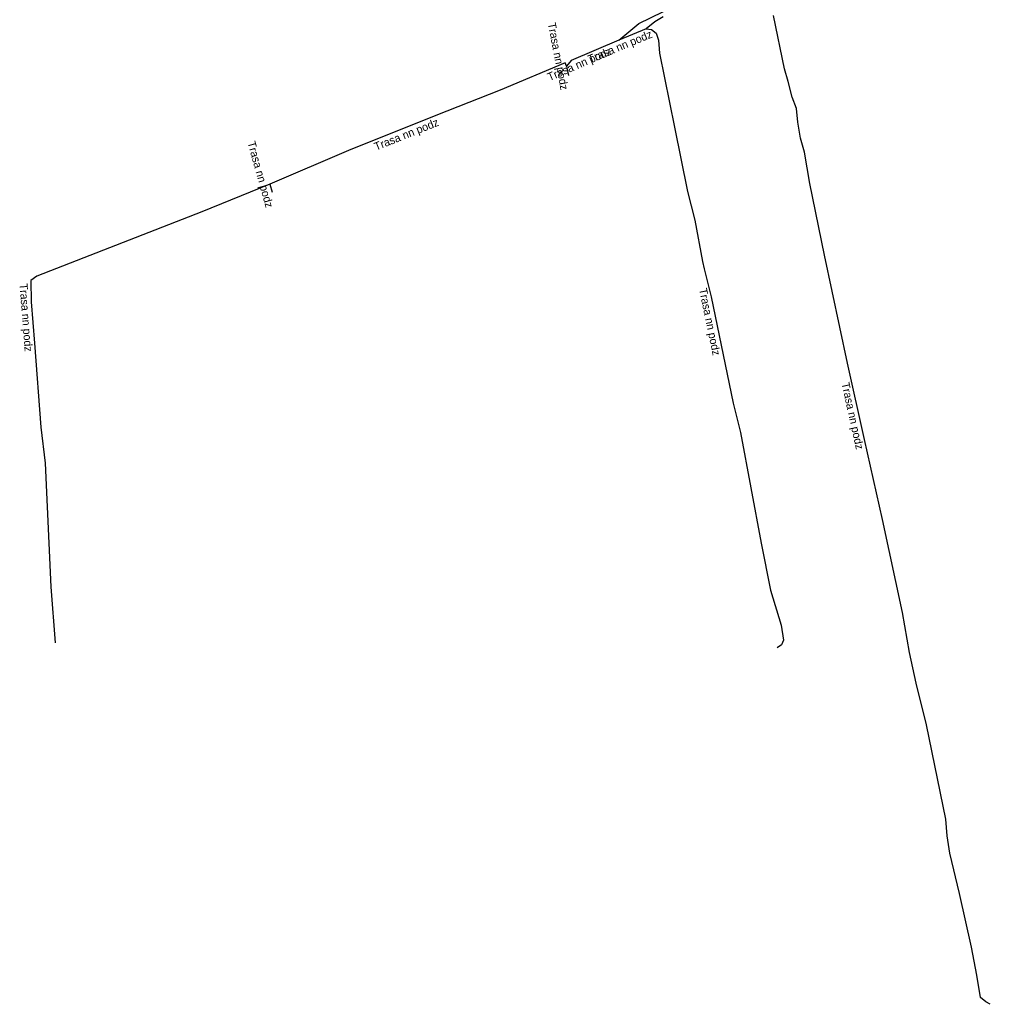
# Model space of a CAD drawing. Extents: x -756855 to -756032, y -1046964 to -1046550.
# Drawn here: x -756747.9 to -756687.3, y -1046964.1 to -1046902.6 of the extents above; entities that cross this region are included whole.
import ezdxf

# ---------------------------------------------------------------- set-up
doc = ezdxf.new("R2010")
doc.units = 0
doc.layers.add('Popiskový text - Ostatní atributy Trasy', color=7, linetype='Continuous')
doc.layers.add('Spojnice NN', color=7, linetype='Continuous')

msp = doc.modelspace()

# ---------------------------------------------------------------- linework, layer by layer
at = {"layer": 'Spojnice NN'}
for points in [[(-756710.52, -1046903.85), (-756709.27, -1046902.82), (-756707.78, -1046902.09), (-756701.58, -1046899.39), (-756698.88, -1046898.62), (-756697.29, -1046898.25), (-756695.54, -1046897.52)], [(-756707.75, -1046902.4), (-756708.28, -1046902.71), (-756708.83, -1046903.15)], [(-756687.33, -1046964.09), (-756687.6, -1046963.93), (-756687.94, -1046963.66), (-756688.17, -1046962.26), (-756688.51, -1046960.53), (-756689.25, -1046957.17), (-756689.85, -1046954.65), (-756690.02, -1046953.56), (-756690.11, -1046952.53), (-756691.32, -1046946.64), (-756691.96, -1046944.03), (-756692.38, -1046942.11), (-756692.81, -1046939.61), (-756694.07, -1046933.81), (-756695.19, -1046928.8), (-756696.24, -1046924.04), (-756697.68, -1046917.29), (-756698.59, -1046912.81), (-756698.94, -1046910.85), (-756699.19, -1046909.97), (-756699.34, -1046908.98), (-756699.43, -1046908.13), (-756699.71, -1046907.41), (-756699.95, -1046906.43), (-756700.18, -1046905.64), (-756700.87, -1046902.32)], [(-756708.83, -1046903.15), (-756710.52, -1046903.85)], [(-756708.83, -1046903.15), (-756708.49, -1046903.19), (-756708.19, -1046903.43), (-756708.06, -1046903.86), (-756707.99, -1046904.67), (-756707.06, -1046909.29), (-756706.24, -1046913.31), (-756705.79, -1046915.11), (-756705.31, -1046917.68), (-756705.19, -1046918.15), (-756704.76, -1046919.9), (-756703.38, -1046926.54), (-756702.94, -1046928.36), (-756701.63, -1046935.28), (-756701.05, -1046938.21), (-756700.4, -1046940.41), (-756700.24, -1046941.35), (-756700.38, -1046941.64), (-756700.65, -1046941.83)], [(-756710.52, -1046903.85), (-756713.5, -1046905.13), (-756713.79, -1046905.49)], [(-756713.79, -1046905.49), (-756713.89, -1046905.28), (-756717.94, -1046906.98), (-756721.28, -1046908.3), (-756725.07, -1046909.82), (-756727.42, -1046910.76), (-756732.32, -1046912.86)], [(-756713.79, -1046905.49), (-756713.68, -1046906.06)], [(-756732.32, -1046912.86), (-756736.57, -1046914.58), (-756746.87, -1046918.6), (-756747.24, -1046918.88), (-756747.22, -1046920.2), (-756747.02, -1046922.78), (-756746.62, -1046928.04), (-756746.36, -1046930.28), (-756746, -1046938.01), (-756745.72, -1046941.51)], [(-756732.32, -1046912.86), (-756732.18, -1046913.36)]]:
    msp.add_lwpolyline(points, dxfattribs=at)

# ---------------------------------------------------------------- texts
at = {"layer": 'Popiskový text - Ostatní atributy Trasy'}
for rotation, p in [(280.9228, (-756714.97, -1046902.808)), (22.49939, (-756712.334, -1046905.305)), (23.24498, (-756714.858, -1046906.421)), (21.85352, (-756725.69, -1046910.769)), (285.64225, (-756733.724, -1046910.254)), (274.43267, (-756747.959, -1046919.077)), (281.74072, (-756705.526, -1046919.409)), (282.43956, (-756696.629, -1046925.293))]:
    msp.add_text('Trasa nn podz', height=0.5, rotation=rotation, dxfattribs=at).set_placement(p)

doc.saveas('drawing.dxf')
